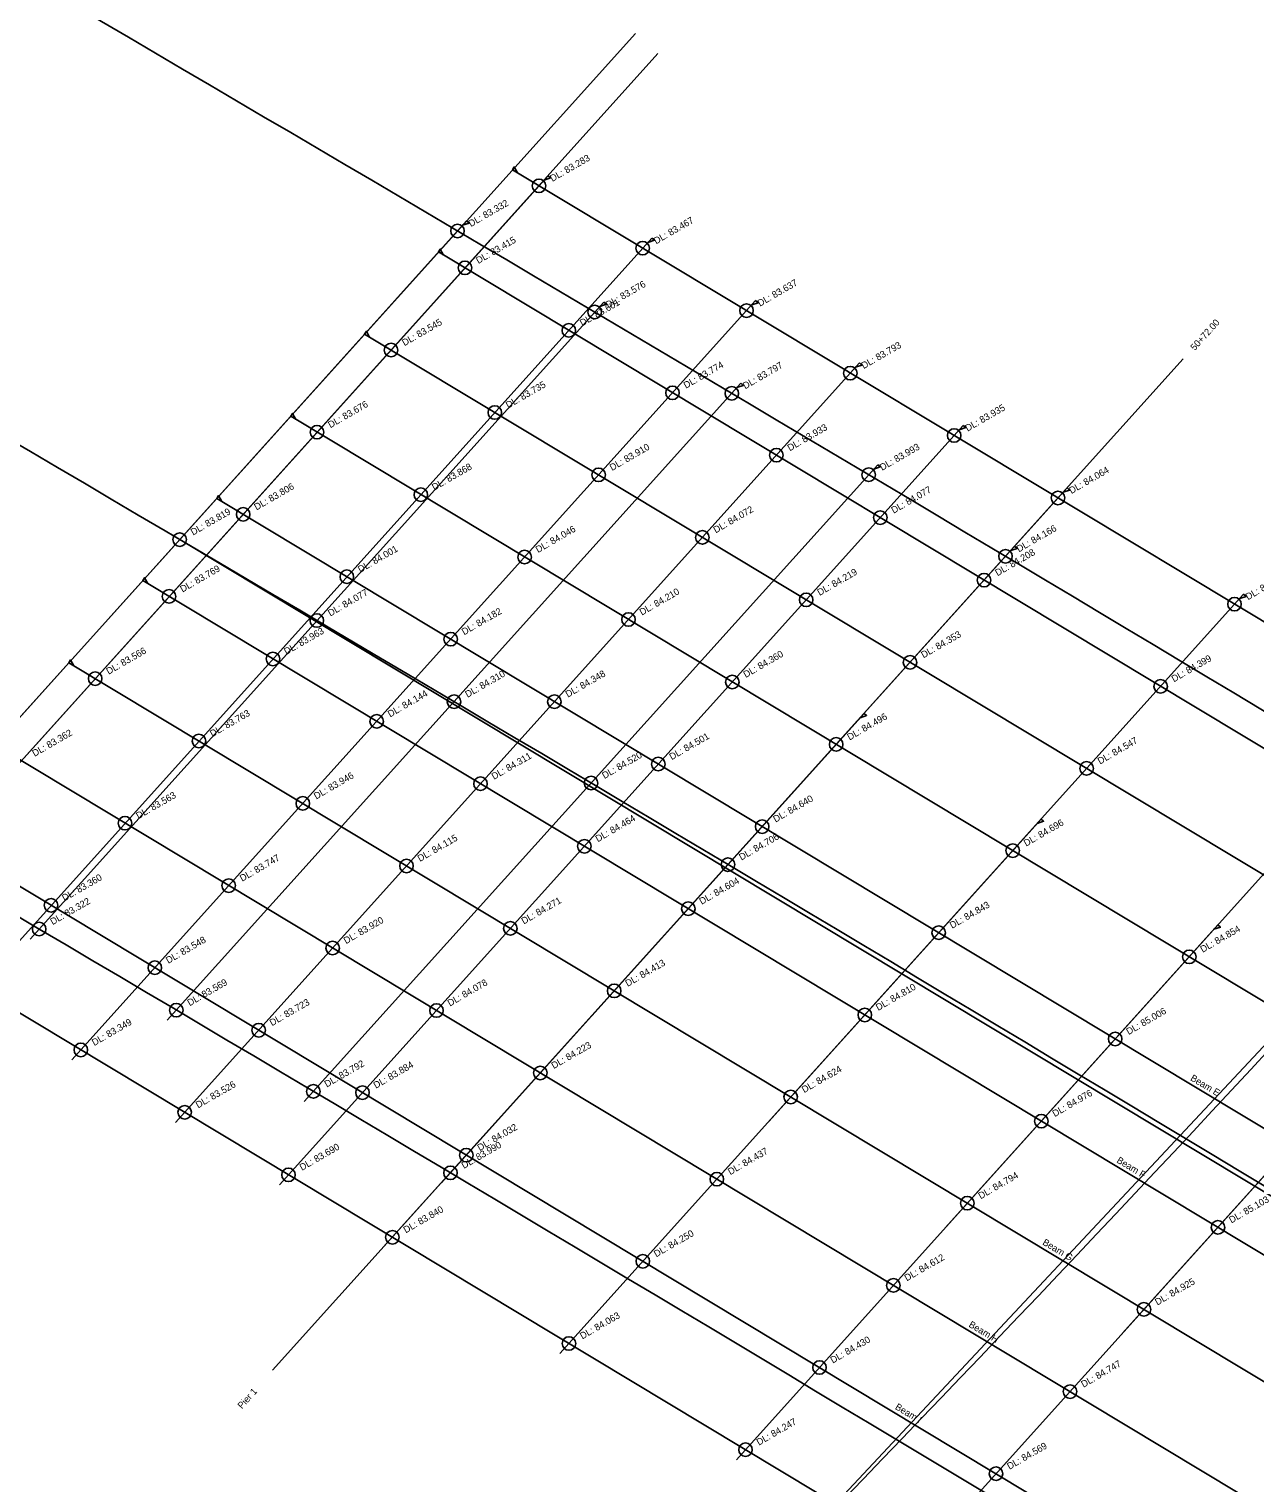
# Model space of a CAD drawing. Extents: x 3599070 to 3599898, y 342469 to 342989.
# Drawn here: x 3599529.9 to 3599620.3, y 342634.7 to 342741.9 of the extents above; entities that cross this region are included whole.
import ezdxf

# ---------------------------------------------------------------- set-up
doc = ezdxf.new("R2010")
doc.units = 0
for name, color, linetype in [('B', 7, 'Continuous'), ('EE', 7, 'Continuous'), ('GUARDRAIL', 7, 'Continuous'), ('PROLINE', 7, 'Continuous'), ('TOE', 7, 'Continuous')]:
    doc.layers.add(name, color=color, linetype=linetype)

msp = doc.modelspace()

# ---------------------------------------------------------------- linework, layer by layer
at = {"layer": 'B'}
for p, q in [((3599576.23, 342740.08), (3599509, 342665.45)), ((3599565.51, 342731.51), (3599711.21, 342643.92)), ((3599560.06, 342725.46), (3599705.75, 342637.87)), ((3599554.6, 342719.4), (3599700.3, 342631.81)), ((3599614.98, 342717.58), (3599547.81, 342643.02)), ((3599549.15, 342713.35), (3599694.84, 342625.76)), ((3599543.69, 342707.29), (3599689.39, 342619.7)), ((3599538.24, 342701.24), (3599683.93, 342613.64)), ((3599532.78, 342695.18), (3599678.48, 342607.59)), ((3599527.33, 342689.13), (3599673.02, 342601.53)), ((3599521.87, 342683.07), (3599667.57, 342595.48)), ((3599516.42, 342677.02), (3599662.11, 342589.42))]:
    msp.add_line(p, q, dxfattribs=at)
for points in [[(3599565.88, 342731.29), (3599565.64, 342731.73), (3599565.51, 342731.51)], [(3599560.43, 342725.23), (3599560.18, 342725.67), (3599560.06, 342725.46)], [(3599554.97, 342719.18), (3599554.73, 342719.62), (3599554.6, 342719.4)], [(3599549.52, 342713.12), (3599549.28, 342713.56), (3599549.15, 342713.35)], [(3599544.06, 342707.07), (3599543.82, 342707.5), (3599543.69, 342707.29)], [(3599538.61, 342701.01), (3599538.37, 342701.45), (3599538.24, 342701.24)], [(3599533.15, 342694.96), (3599532.91, 342695.39), (3599532.78, 342695.18)]]:
    msp.add_lwpolyline(points, dxfattribs=at)
at = {"layer": 'EE'}
for points in [[(3599568.13, 342731.08), (3599517.7, 342675.1)], [(3599567.84, 342730.76), (3599568.31, 342730.92), (3599568.13, 342731.08)], [(3599562.12, 342727.75), (3599519.8, 342680.77)], [(3599561.83, 342727.43), (3599562.31, 342727.58), (3599562.12, 342727.75)], [(3599575.78, 342726.48), (3599525.35, 342670.5)], [(3599575.49, 342726.16), (3599575.97, 342726.32), (3599575.78, 342726.48)], [(3599572.24, 342721.77), (3599529.93, 342674.81)], [(3599583.44, 342721.88), (3599533, 342665.9)], [(3599571.95, 342721.45), (3599572.42, 342721.61), (3599572.24, 342721.77)], [(3599583.15, 342721.56), (3599583.62, 342721.71), (3599583.44, 342721.88)], [(3599591.09, 342717.28), (3599540.66, 342661.3)], [(3599590.8, 342716.96), (3599591.28, 342717.11), (3599591.09, 342717.28)], [(3599582.35, 342715.79), (3599540.04, 342668.83)], [(3599582.06, 342715.46), (3599582.53, 342715.62), (3599582.35, 342715.79)], [(3599598.75, 342712.67), (3599548.32, 342656.69)], [(3599598.46, 342712.35), (3599598.94, 342712.51), (3599598.75, 342712.67)], [(3599592.45, 342709.78), (3599550.15, 342662.84)], [(3599592.16, 342709.46), (3599592.63, 342709.62), (3599592.45, 342709.78)], [(3599606.41, 342708.07), (3599555.98, 342652.09)], [(3599606.12, 342707.75), (3599606.6, 342707.9), (3599606.41, 342708.07)], [(3599602.54, 342703.77), (3599560.26, 342656.84)], [(3599602.25, 342703.45), (3599602.72, 342703.6), (3599602.54, 342703.77)], [(3599619.43, 342700.24), (3599569, 342644.26)], [(3599619.14, 342699.92), (3599619.61, 342700.07), (3599619.43, 342700.24)], [(3599632.45, 342692.41), (3599582.02, 342636.43)], [(3599591.44, 342691.45), (3599571.36, 342669.16)], [(3599591.15, 342691.13), (3599591.62, 342691.28), (3599591.44, 342691.45)], [(3599604.49, 342683.66), (3599584.41, 342661.37)], [(3599645.48, 342684.58), (3599595.05, 342628.6)], [(3599604.2, 342683.34), (3599604.68, 342683.49), (3599604.49, 342683.66)], [(3599617.53, 342675.85), (3599597.45, 342653.56)], [(3599617.24, 342675.53), (3599617.72, 342675.68), (3599617.53, 342675.85)], [(3599630.56, 342668.01), (3599610.48, 342645.73)]]:
    msp.add_lwpolyline(points, dxfattribs=at)
for centre in [(3599567.46, 342730.34), (3599561.45, 342727.01), (3599575.11, 342725.74), (3599562, 342724.29), (3599571.57, 342721.03), (3599582.77, 342721.14), (3599569.66, 342719.68), (3599556.55, 342718.23), (3599590.42, 342716.53), (3599577.31, 342715.08), (3599581.68, 342715.04), (3599564.2, 342713.63), (3599551.09, 342712.18), (3599598.08, 342711.93), (3599584.97, 342710.48), (3599571.86, 342709.03), (3599591.78, 342709.04), (3599558.75, 342707.57), (3599605.74, 342707.33), (3599545.64, 342706.12), (3599592.63, 342705.88), (3599540.96, 342704.26), (3599579.51, 342704.42), (3599566.4, 342702.97), (3599601.87, 342703.03), (3599553.29, 342701.52), (3599600.29, 342701.27), (3599540.18, 342700.07), (3599587.17, 342699.82), (3599618.76, 342699.5), (3599551.08, 342698.29), (3599574.06, 342698.37), (3599560.95, 342696.92), (3599547.84, 342695.46), (3599594.83, 342695.21), (3599534.73, 342694.01), (3599581.72, 342693.76), (3599613.31, 342693.44), (3599561.2, 342692.31), (3599568.6, 342692.31), (3599555.49, 342690.86), (3599542.38, 342689.41), (3599589.38, 342689.16), (3599576.26, 342687.71), (3599607.85, 342687.39), (3599563.15, 342686.26), (3599571.3, 342686.31), (3599550.04, 342684.81), (3599536.93, 342683.35), (3599583.92, 342683.1), (3599570.81, 342681.65), (3599602.4, 342681.33), (3599557.69, 342680.2), (3599581.4, 342680.3), (3599544.58, 342678.75), (3599531.47, 342677.3), (3599578.47, 342677.05), (3599530.6, 342675.55), (3599565.35, 342675.6), (3599596.94, 342675.28), (3599552.24, 342674.15), (3599615.42, 342673.5), (3599539.13, 342672.7), (3599573.01, 342670.99), (3599540.71, 342669.57), (3599559.9, 342669.54), (3599591.49, 342669.22), (3599546.79, 342668.09), (3599609.96, 342667.45), (3599533.67, 342666.64), (3599567.56, 342664.94), (3599550.82, 342663.58), (3599554.44, 342663.49), (3599586.03, 342663.17), (3599541.33, 342662.04), (3599604.51, 342661.39), (3599562.1, 342658.88), (3599548.99, 342657.43), (3599560.93, 342657.58), (3599580.58, 342657.11), (3599599.05, 342655.34), (3599617.54, 342653.56), (3599556.65, 342652.83), (3599575.12, 342651.06), (3599593.6, 342649.28), (3599612.08, 342647.51), (3599569.67, 342645), (3599588.15, 342643.23), (3599606.63, 342641.45), (3599582.69, 342637.17), (3599601.17, 342635.4)]:
    msp.add_circle(centre, 0.499, dxfattribs=at)
at = {"layer": 'GUARDRAIL'}
for p, q in [((3599574.58, 342741.57), (3599507.35, 342666.95)), ((3599614.98, 342717.58), (3599547.81, 342643.02)), ((3599540.96, 342704.26), (3599686.66, 342616.67))]:
    msp.add_line(p, q, dxfattribs=at)
for centre, radius, start, end in [((3594639.68, 334386.71), 9684.24, 58.937083, 60.687623), ((3594639.68, 334386.71), 9654.24, 58.937083, 60.687778), ((3594639.68, 334386.71), 9624.24, 58.937083, 60.687637), ((3597781.98, 344376.76), 2511.5, 311.2043, 317.27688), ((3597781.98, 344376.76), 2511.5, 311.2043, 317.27688), ((3597781.98, 344376.76), 2511.5, 311.2043, 317.27688), ((3597781.98, 344376.76), 2511.5, 311.2043, 317.27688), ((3597781.98, 344376.76), 2511.5, 311.2043, 317.27688), ((3597781.98, 344376.76), 2511.5, 311.2043, 317.27688), ((3597781.98, 344376.76), 2511.5, 311.2043, 317.27688), ((3597781.98, 344376.76), 2511.5, 311.2043, 317.27688), ((3597781.98, 344376.76), 2511.5, 311.2043, 317.27688), ((3597781.98, 344376.76), 2511.5, 311.2043, 317.27688)]:
    msp.add_arc(centre, radius, start, end, dxfattribs=at)
at = {"layer": 'PROLINE'}
msp.add_line((3599643.56, 342691.1), (3599574.7, 342617.56), dxfattribs=at)

# ---------------------------------------------------------------- texts
at = {"layer": 'B'}
for s, p in [('Beam E', (3599615.46, 342664.43)), ('Beam F', (3599610.02, 342658.37)), ('Beam G', (3599604.55, 342652.32)), ('Beam H', (3599599.11, 342646.26)), ('Beam I', (3599593.68, 342640.19))]:
    msp.add_text(s, height=0.499, rotation=328.986, dxfattribs=at).set_placement(p)
at = {"layer": 'EE'}
for s, p in [('DL: 83.283', (3599568.45, 342730.62)), ('DL: 83.332', (3599562.44, 342727.29)), ('DL: 83.467', (3599576.1, 342726.02)), ('DL: 83.415', (3599562.99, 342724.57)), ('DL: 83.576', (3599572.56, 342721.31)), ('DL: 83.637', (3599583.76, 342721.42)), ('DL: 83.601', (3599570.65, 342719.97)), ('DL: 83.545', (3599557.54, 342718.51)), ('DL: 83.793', (3599591.41, 342716.82)), ('DL: 83.774', (3599578.3, 342715.37)), ('DL: 83.797', (3599582.67, 342715.33)), ('DL: 83.735', (3599565.19, 342713.91)), ('DL: 83.676', (3599552.08, 342712.46)), ('DL: 83.935', (3599599.07, 342712.21)), ('DL: 83.933', (3599585.96, 342710.76)), ('DL: 83.910', (3599572.85, 342709.31)), ('DL: 83.993', (3599592.77, 342709.32)), ('DL: 83.868', (3599559.74, 342707.86)), ('DL: 84.064', (3599606.73, 342707.61)), ('DL: 83.806', (3599546.63, 342706.4)), ('DL: 84.077', (3599593.62, 342706.16)), ('DL: 83.819', (3599541.95, 342704.55)), ('DL: 84.072', (3599580.5, 342704.71)), ('DL: 84.046', (3599567.39, 342703.26)), ('DL: 84.166', (3599602.86, 342703.31)), ('DL: 84.001', (3599554.28, 342701.8)), ('DL: 84.208', (3599601.28, 342701.55)), ('DL: 83.769', (3599541.17, 342700.35)), ('DL: 84.219', (3599588.16, 342700.1)), ('DL: 84.250', (3599619.75, 342699.78)), ('DL: 84.077', (3599552.07, 342698.58)), ('DL: 84.210', (3599575.05, 342698.65)), ('DL: 84.182', (3599561.94, 342697.2)), ('DL: 83.963', (3599548.83, 342695.75)), ('DL: 84.353', (3599595.82, 342695.5)), ('DL: 83.566', (3599535.72, 342694.29)), ('DL: 84.360', (3599582.71, 342694.05)), ('DL: 84.399', (3599614.29, 342693.73)), ('DL: 84.310', (3599562.19, 342692.59)), ('DL: 84.348', (3599569.59, 342692.6)), ('DL: 84.144', (3599556.48, 342691.14)), ('DL: 83.763', (3599543.37, 342689.69)), ('DL: 84.496', (3599590.37, 342689.44)), ('DL: 83.362', (3599530.26, 342688.24)), ('DL: 84.501', (3599577.25, 342687.99)), ('DL: 84.547', (3599608.84, 342687.67)), ('DL: 84.311', (3599564.14, 342686.54)), ('DL: 84.520', (3599572.29, 342686.6)), ('DL: 83.946', (3599551.03, 342685.09)), ('DL: 83.563', (3599537.92, 342683.64)), ('DL: 84.640', (3599584.91, 342683.39)), ('DL: 84.464', (3599571.8, 342681.94)), ('DL: 84.696', (3599603.39, 342681.62)), ('DL: 84.115', (3599558.68, 342680.49)), ('DL: 84.706', (3599582.39, 342680.59)), ('DL: 83.747', (3599545.57, 342679.03)), ('DL: 83.360', (3599532.46, 342677.58)), ('DL: 84.604', (3599579.46, 342677.33)), ('DL: 83.322', (3599531.59, 342675.83)), ('DL: 84.271', (3599566.34, 342675.88)), ('DL: 84.843', (3599597.93, 342675.56)), ('DL: 83.920', (3599553.23, 342674.43)), ('DL: 83.548', (3599540.12, 342672.98)), ('DL: 84.854', (3599616.41, 342673.79)), ('DL: 84.413', (3599574, 342671.28)), ('DL: 83.569', (3599541.7, 342669.85)), ('DL: 84.078', (3599560.89, 342669.83)), ('DL: 84.810', (3599592.48, 342669.51)), ('DL: 83.723', (3599547.77, 342668.38)), ('DL: 85.006', (3599610.95, 342667.73)), ('DL: 83.349', (3599534.66, 342666.92)), ('DL: 84.223', (3599568.55, 342665.22)), ('DL: 83.792', (3599551.81, 342663.86)), ('DL: 83.884', (3599555.43, 342663.77)), ('DL: 84.624', (3599587.02, 342663.45)), ('DL: 83.526', (3599542.32, 342662.32)), ('DL: 84.976', (3599605.5, 342661.68)), ('DL: 84.032', (3599563.09, 342659.17)), ('DL: 83.690', (3599549.98, 342657.72)), ('DL: 83.990', (3599561.92, 342657.86)), ('DL: 84.437', (3599581.57, 342657.4)), ('DL: 84.794', (3599600.04, 342655.62)), ('DL: 85.103', (3599618.53, 342653.84)), ('DL: 83.840', (3599557.64, 342653.11)), ('DL: 84.250', (3599576.11, 342651.34)), ('DL: 84.612', (3599594.59, 342649.57)), ('DL: 84.925', (3599613.07, 342647.79)), ('DL: 84.063', (3599570.66, 342645.29)), ('DL: 84.430', (3599589.13, 342643.51)), ('DL: 84.747', (3599607.62, 342641.73)), ('DL: 84.247', (3599583.68, 342637.46)), ('DL: 84.569', (3599602.16, 342635.68))]:
    msp.add_text(s, height=0.499, rotation=30, dxfattribs=at).set_placement(p)
at = {"layer": 'TOE'}
for s, p in [('50+72.00', (3599615.83, 342718.15)), ('Pier 1', (3599545.55, 342640.14))]:
    msp.add_text(s, height=0.499, rotation=47.9859, dxfattribs=at).set_placement(p)

doc.saveas('drawing.dxf')
